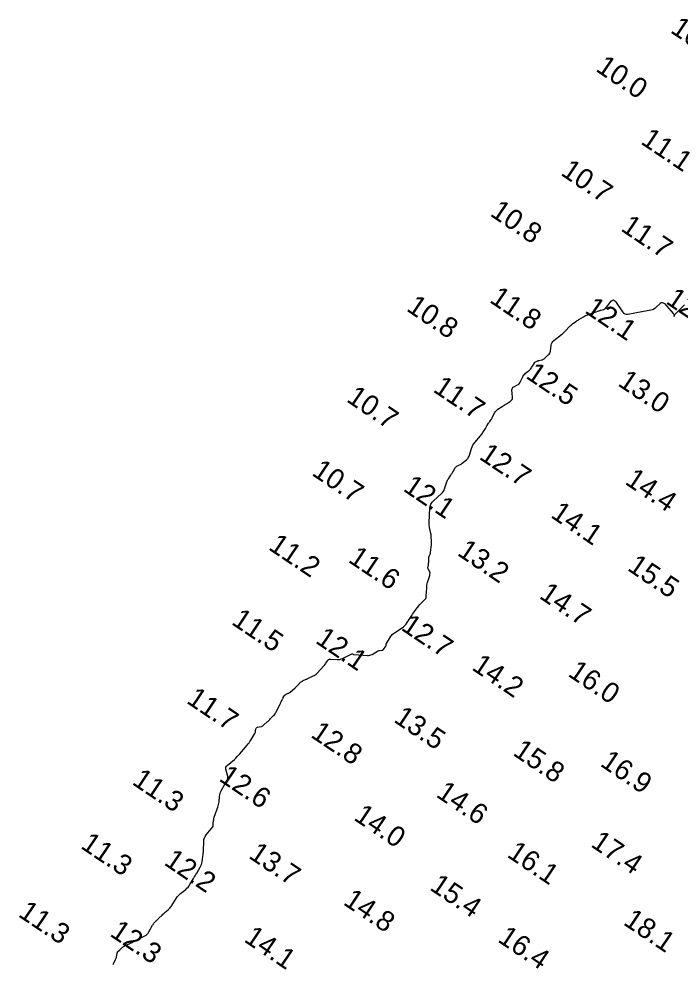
# Model space of a CAD drawing. Extents: x 815352 to 820877, y 582403 to 597439.
# Drawn here: x 816988.9 to 817151.9, y 584926.9 to 585160 of the extents above; entities that cross this region are included whole.
import ezdxf

# ---------------------------------------------------------------- set-up
doc = ezdxf.new("R2010")
doc.units = 0
doc.layers.add('V-CONT-EL12', color=7, linetype='Continuous')
doc.layers.add('V-TOPO-SOUN', color=7, linetype='Continuous')

msp = doc.modelspace()

# ---------------------------------------------------------------- linework, layer by layer
at = {"layer": 'V-CONT-EL12'}
msp.add_lwpolyline([(817012.1, 584926.85), (817012.19, 584927.02), (817012.69, 584928.03), (817012.77, 584928.2), (817012.83, 584928.37), (817012.88, 584928.55), (817012.92, 584928.73), (817013.05, 584929.56), (817013.08, 584929.69), (817013.13, 584929.82), (817013.2, 584929.93), (817013.28, 584930.03), (817013.7, 584930.45), (817013.79, 584930.54), (817013.87, 584930.62), (817013.96, 584930.7), (817014.06, 584930.78), (817014.43, 584931.1), (817014.52, 584931.18), (817014.62, 584931.25), (817014.73, 584931.31), (817014.83, 584931.37), (817016.72, 584932.29), (817017.07, 584932.47), (817017.42, 584932.64), (817017.77, 584932.82), (817018.12, 584932.99), (817019.89, 584933.88), (817020.21, 584934.07), (817020.49, 584934.3), (817020.73, 584934.57), (817020.93, 584934.89), (817021.82, 584936.55), (817021.92, 584936.71), (817022.02, 584936.87), (817022.14, 584937.02), (817022.27, 584937.15), (817022.82, 584937.69), (817022.96, 584937.82), (817023.09, 584937.96), (817023.23, 584938.09), (817023.37, 584938.22), (817024.19, 584939.03), (817024.37, 584939.21), (817024.56, 584939.39), (817024.75, 584939.56), (817024.95, 584939.73), (817025.74, 584940.39), (817025.93, 584940.57), (817026.1, 584940.75), (817026.26, 584940.95), (817026.4, 584941.16), (817027.65, 584943.14), (817027.88, 584943.48), (817028.13, 584943.79), (817028.41, 584944.07), (817028.71, 584944.34), (817029.98, 584945.35), (817030.28, 584945.62), (817030.56, 584945.91), (817030.8, 584946.22), (817031.02, 584946.56), (817031.88, 584948), (817032.08, 584948.34), (817032.29, 584948.68), (817032.49, 584949.03), (817032.69, 584949.37), (817033.56, 584950.83), (817033.72, 584951.14), (817033.86, 584951.46), (817033.95, 584951.79), (817034.02, 584952.14), (817034.22, 584953.53), (817034.27, 584953.88), (817034.3, 584954.23), (817034.33, 584954.58), (817034.35, 584954.93), (817034.44, 584957.21), (817034.49, 584957.64), (817034.61, 584958.05), (817034.8, 584958.43), (817035.05, 584958.78), (817036.68, 584960.74), (817036.71, 584960.79), (817036.74, 584960.85), (817036.75, 584960.9), (817036.75, 584960.97), (817036.74, 584961.26), (817036.74, 584961.3), (817036.74, 584961.34), (817036.75, 584961.38), (817036.75, 584961.42), (817036.77, 584961.58), (817036.78, 584961.62), (817036.79, 584961.66), (817036.79, 584961.7), (817036.79, 584961.74), (817036.88, 584962.6), (817036.9, 584962.75), (817036.93, 584962.91), (817036.96, 584963.06), (817037.01, 584963.2), (817037.89, 584965.65), (817037.99, 584965.98), (817038.08, 584966.31), (817038.15, 584966.64), (817038.2, 584966.98), (817038.34, 584968.35), (817038.4, 584968.68), (817038.48, 584969.01), (817038.6, 584969.33), (817038.75, 584969.63), (817039.64, 584971.26), (817039.7, 584971.37), (817039.76, 584971.48), (817039.83, 584971.59), (817039.9, 584971.7), (817040.19, 584972.15), (817040.25, 584972.25), (817040.29, 584972.35), (817040.32, 584972.46), (817040.33, 584972.57), (817040.34, 584973.03), (817040.34, 584973.14), (817040.33, 584973.26), (817040.32, 584973.37), (817040.29, 584973.48), (817039.91, 584974.98), (817039.87, 584975.25), (817039.91, 584975.5), (817040.02, 584975.73), (817040.21, 584975.93), (817041.98, 584977.42), (817042.34, 584977.74), (817042.69, 584978.08), (817043.03, 584978.43), (817043.35, 584978.79), (817045.15, 584980.91), (817045.39, 584981.21), (817045.61, 584981.51), (817045.83, 584981.82), (817046.02, 584982.14), (817047.03, 584983.83), (817047.1, 584983.96), (817047.15, 584984.09), (817047.2, 584984.24), (817047.22, 584984.38), (817047.31, 584984.98), (817047.35, 584985.12), (817047.42, 584985.22), (817047.52, 584985.29), (817047.66, 584985.33), (817048.5, 584985.49), (817048.69, 584985.54), (817048.86, 584985.61), (817049.02, 584985.7), (817049.17, 584985.82), (817050.16, 584986.71), (817050.36, 584986.89), (817050.55, 584987.08), (817050.74, 584987.26), (817050.92, 584987.45), (817051.66, 584988.22), (817051.84, 584988.42), (817052, 584988.63), (817052.14, 584988.85), (817052.27, 584989.09), (817053.26, 584991.1), (817053.32, 584991.23), (817053.39, 584991.36), (817053.45, 584991.49), (817053.51, 584991.62), (817053.77, 584992.14), (817053.84, 584992.27), (817053.91, 584992.4), (817053.98, 584992.52), (817054.05, 584992.64), (817054.35, 584993.13), (817054.44, 584993.24), (817054.53, 584993.33), (817054.64, 584993.41), (817054.76, 584993.48), (817055.28, 584993.7), (817055.41, 584993.76), (817055.53, 584993.83), (817055.65, 584993.91), (817055.76, 584993.99), (817056.96, 584995.03), (817057.09, 584995.14), (817057.21, 584995.26), (817057.33, 584995.39), (817057.45, 584995.52), (817058, 584996.16), (817058.07, 584996.23), (817058.14, 584996.3), (817058.21, 584996.36), (817058.29, 584996.41), (817058.62, 584996.62), (817058.71, 584996.68), (817058.79, 584996.73), (817058.88, 584996.77), (817058.97, 584996.82), (817059.55, 584997.1), (817059.68, 584997.16), (817059.81, 584997.23), (817059.94, 584997.29), (817060.06, 584997.35), (817061.43, 584997.98), (817061.69, 584998.12), (817061.94, 584998.28), (817062.16, 584998.46), (817062.37, 584998.67), (817064.01, 585000.44), (817064.15, 585000.6), (817064.28, 585000.76), (817064.41, 585000.93), (817064.53, 585001.1), (817065, 585001.81), (817065.13, 585001.96), (817065.29, 585002.07), (817065.46, 585002.12), (817065.66, 585002.14), (817067.31, 585002.04), (817067.65, 585002.04), (817067.98, 585002.08), (817068.3, 585002.17), (817068.62, 585002.29), (817070.98, 585003.4), (817071.02, 585003.42), (817071.06, 585003.42), (817071.1, 585003.42), (817071.14, 585003.4), (817071.31, 585003.32), (817071.35, 585003.3), (817071.39, 585003.29), (817071.44, 585003.28), (817071.48, 585003.27), (817074.77, 585003.03), (817075.08, 585003.03), (817075.37, 585003.07), (817075.65, 585003.16), (817075.92, 585003.29), (817077.29, 585004.1), (817077.4, 585004.16), (817077.53, 585004.21), (817077.65, 585004.24), (817077.78, 585004.26), (817078.32, 585004.3), (817078.45, 585004.33), (817078.56, 585004.38), (817078.66, 585004.45), (817078.75, 585004.54), (817079.31, 585005.32), (817079.34, 585005.37), (817079.37, 585005.42), (817079.38, 585005.47), (817079.39, 585005.52), (817079.4, 585005.74), (817079.41, 585005.8), (817079.42, 585005.85), (817079.44, 585005.9), (817079.47, 585005.95), (817080.5, 585007.64), (817080.7, 585007.92), (817080.92, 585008.18), (817081.18, 585008.41), (817081.45, 585008.61), (817083.33, 585009.84), (817083.71, 585010.12), (817084.05, 585010.43), (817084.35, 585010.78), (817084.62, 585011.16), (817085.72, 585012.92), (817085.92, 585013.24), (817086.14, 585013.55), (817086.36, 585013.86), (817086.59, 585014.16), (817087.74, 585015.59), (817087.88, 585015.76), (817088.03, 585015.93), (817088.18, 585016.1), (817088.33, 585016.25), (817089.19, 585017.12), (817089.23, 585017.16), (817089.25, 585017.21), (817089.27, 585017.26), (817089.27, 585017.31), (817089.28, 585017.53), (817089.29, 585017.59), (817089.29, 585017.64), (817089.29, 585017.7), (817089.3, 585017.76), (817089.4, 585019.68), (817089.43, 585020.01), (817089.47, 585020.34), (817089.54, 585020.67), (817089.63, 585021), (817090.16, 585022.79), (817090.18, 585022.86), (817090.19, 585022.94), (817090.2, 585023.01), (817090.21, 585023.09), (817090.23, 585023.4), (817090.23, 585023.47), (817090.22, 585023.54), (817090.2, 585023.61), (817090.16, 585023.68), (817089.82, 585024.2), (817089.76, 585024.31), (817089.73, 585024.43), (817089.71, 585024.55), (817089.72, 585024.68), (817089.83, 585025.37), (817089.85, 585025.53), (817089.87, 585025.69), (817089.88, 585025.84), (817089.89, 585026), (817089.96, 585027.25), (817089.97, 585027.36), (817089.99, 585027.46), (817090.02, 585027.55), (817090.06, 585027.65), (817090.23, 585028.02), (817090.27, 585028.12), (817090.3, 585028.21), (817090.33, 585028.31), (817090.34, 585028.42), (817090.55, 585030.36), (817090.57, 585030.59), (817090.58, 585030.82), (817090.59, 585031.05), (817090.58, 585031.28), (817090.54, 585032.21), (817090.53, 585032.44), (817090.5, 585032.67), (817090.47, 585032.9), (817090.42, 585033.13), (817090.12, 585034.55), (817090.07, 585034.86), (817090.03, 585035.17), (817090.02, 585035.49), (817090.02, 585035.81), (817090.2, 585039.33), (817090.28, 585039.86), (817090.45, 585040.36), (817090.73, 585040.8), (817091.09, 585041.2), (817093.06, 585042.98), (817093.31, 585043.24), (817093.52, 585043.52), (817093.69, 585043.83), (817093.83, 585044.16), (817094.37, 585045.84), (817094.45, 585046.04), (817094.53, 585046.23), (817094.63, 585046.41), (817094.74, 585046.59), (817095.22, 585047.28), (817095.33, 585047.46), (817095.45, 585047.64), (817095.55, 585047.82), (817095.66, 585048), (817096.3, 585049.16), (817096.41, 585049.32), (817096.53, 585049.46), (817096.67, 585049.58), (817096.84, 585049.68), (817097.53, 585050.03), (817097.7, 585050.13), (817097.87, 585050.23), (817098.03, 585050.34), (817098.18, 585050.46), (817099.22, 585051.31), (817099.43, 585051.5), (817099.6, 585051.72), (817099.74, 585051.96), (817099.85, 585052.22), (817100.48, 585054.11), (817100.63, 585054.5), (817100.82, 585054.88), (817101.04, 585055.24), (817101.3, 585055.57), (817102.69, 585057.22), (817102.85, 585057.42), (817103, 585057.62), (817103.15, 585057.83), (817103.28, 585058.04), (817103.9, 585059.03), (817103.99, 585059.18), (817104.08, 585059.33), (817104.17, 585059.48), (817104.25, 585059.63), (817104.64, 585060.3), (817104.71, 585060.42), (817104.78, 585060.54), (817104.86, 585060.66), (817104.94, 585060.77), (817105.28, 585061.22), (817105.36, 585061.34), (817105.44, 585061.45), (817105.51, 585061.57), (817105.58, 585061.7), (817106.24, 585062.95), (817106.38, 585063.19), (817106.55, 585063.4), (817106.75, 585063.59), (817106.97, 585063.76), (817108.02, 585064.46), (817108.28, 585064.62), (817108.53, 585064.79), (817108.79, 585064.95), (817109.04, 585065.12), (817110.08, 585065.78), (817110.31, 585065.96), (817110.46, 585066.18), (817110.54, 585066.43), (817110.56, 585066.72), (817110.43, 585068.55), (817110.45, 585068.79), (817110.52, 585068.99), (817110.66, 585069.16), (817110.86, 585069.29), (817111.78, 585069.76), (817112, 585069.89), (817112.18, 585070.05), (817112.34, 585070.24), (817112.46, 585070.46), (817113.07, 585071.75), (817113.21, 585072), (817113.37, 585072.23), (817113.56, 585072.44), (817113.77, 585072.63), (817114.76, 585073.42), (817114.93, 585073.58), (817115.09, 585073.74), (817115.23, 585073.93), (817115.36, 585074.12), (817115.95, 585075.15), (817116.01, 585075.24), (817116.08, 585075.32), (817116.16, 585075.38), (817116.26, 585075.44), (817116.66, 585075.62), (817116.76, 585075.67), (817116.87, 585075.7), (817116.97, 585075.74), (817117.08, 585075.76), (817117.79, 585075.92), (817117.94, 585075.97), (817118.08, 585076.03), (817118.21, 585076.11), (817118.33, 585076.2), (817119.39, 585077.14), (817119.58, 585077.34), (817119.73, 585077.57), (817119.84, 585077.82), (817119.9, 585078.09), (817120.11, 585079.59), (817120.19, 585079.92), (817120.32, 585080.21), (817120.51, 585080.48), (817120.76, 585080.71), (817122.63, 585082.17), (817122.89, 585082.38), (817123.14, 585082.6), (817123.38, 585082.83), (817123.61, 585083.07), (817124.65, 585084.19), (817124.81, 585084.36), (817124.99, 585084.52), (817125.17, 585084.67), (817125.36, 585084.81), (817126.15, 585085.36), (817126.34, 585085.49), (817126.54, 585085.62), (817126.74, 585085.75), (817126.95, 585085.88), (817128.07, 585086.56), (817128.32, 585086.71), (817128.59, 585086.84), (817128.86, 585086.96), (817129.14, 585087.07), (817131.88, 585088.05), (817132.02, 585088.1), (817132.15, 585088.14), (817132.29, 585088.18), (817132.43, 585088.21), (817132.99, 585088.32), (817133.12, 585088.36), (817133.25, 585088.42), (817133.35, 585088.5), (817133.45, 585088.6), (817134.91, 585090.38), (817135.18, 585090.62), (817135.44, 585090.7), (817135.7, 585090.6), (817135.94, 585090.33), (817137.68, 585087.76), (817137.94, 585087.45), (817138.25, 585087.26), (817138.61, 585087.17), (817139.01, 585087.2), (817140.72, 585087.51), (817141.14, 585087.58), (817141.57, 585087.66), (817142, 585087.74), (817142.42, 585087.82), (817144.69, 585088.23), (817145.04, 585088.32), (817145.36, 585088.46), (817145.66, 585088.64), (817145.93, 585088.86), (817146.98, 585089.85), (817147.24, 585090.04), (817147.5, 585090.09), (817147.75, 585090.02), (817148, 585089.81), (817150.2, 585087.39), (817150.32, 585087.23), (817150.39, 585087.04), (817150.42, 585086.85), (817150.39, 585086.64), (817150.45, 585086.85), (817150.54, 585087.04), (817150.66, 585087.22), (817150.8, 585087.38), (817152.94, 585089.52)], dxfattribs=at)

# ---------------------------------------------------------------- texts
at = {"layer": 'V-TOPO-SOUN'}
for s, p in [('10.5 ', (817149.26, 585156.83)), ('10.0 ', (817130.86, 585147.3)), ('11.1 ', (817141.94, 585129.38)), ('10.7 ', (817122.22, 585121.66)), ('10.8 ', (817104.8, 585111.62)), ('11.7 ', (817137.02, 585107.95)), ('11.8 ', (817104.67, 585090.3)), ('10.8 ', (817084.17, 585088.2)), ('12.2 ', (817148.14, 585090)), ('12.1 ', (817128.13, 585087.72)), ('12.5 ', (817113.6, 585071.6)), ('13.0 ', (817136.3, 585069.74)), ('11.7 ', (817090.73, 585068.25)), ('10.7 ', (817069.37, 585065.82)), ('12.7 ', (817102.11, 585051.65)), ('10.7 ', (817060.84, 585047.65)), ('12.1 ', (817083.34, 585043.79)), ('14.4 ', (817138.04, 585045.48)), ('14.1 ', (817119.73, 585037.26)), ('11.2 ', (817050.14, 585029.34)), ('13.2 ', (817096.7, 585027.93)), ('11.6 ', (817069.8, 585026.25)), ('15.5 ', (817138.63, 585024.22)), ('14.7 ', (817116.91, 585017.33)), ('11.5 ', (817041.02, 585010.9)), ('12.7 ', (817082.85, 585009.49)), ('12.1 ', (817061.72, 585006.29)), ('14.2 ', (817100.28, 584999.68)), ('16.0 ', (817124, 584998.12)), ('11.7 ', (817029.93, 584991.48)), ('13.5 ', (817081.02, 584986.82)), ('12.8 ', (817060.55, 584983.08)), ('15.8 ', (817110.41, 584978.62)), ('16.9 ', (817131.94, 584975.96)), ('11.3 ', (817016.52, 584971.43)), ('12.6 ', (817037.94, 584972.31)), ('14.6 ', (817091.48, 584968.34)), ('14.0 ', (817071.18, 584962.65)), ('11.3 ', (817003.82, 584955.69)), ('17.4 ', (817129.61, 584956.08)), ('13.7 ', (817045.26, 584953.26)), ('16.1 ', (817108.97, 584953.53)), ('12.2 ', (817024.39, 584951.58)), ('15.4 ', (817089.91, 584945.42)), ('14.8 ', (817068.58, 584941.77)), ('11.3 ', (816988.43, 584938.85)), ('18.1 ', (817137.64, 584936.83)), ('12.3 ', (817011.04, 584934.03)), ('14.1 ', (817044.1, 584932.63)), ('16.4 ', (817106.67, 584932.62))]:
    msp.add_text(s, height=5, rotation=326, dxfattribs=at).set_placement(p)

doc.saveas('drawing.dxf')
